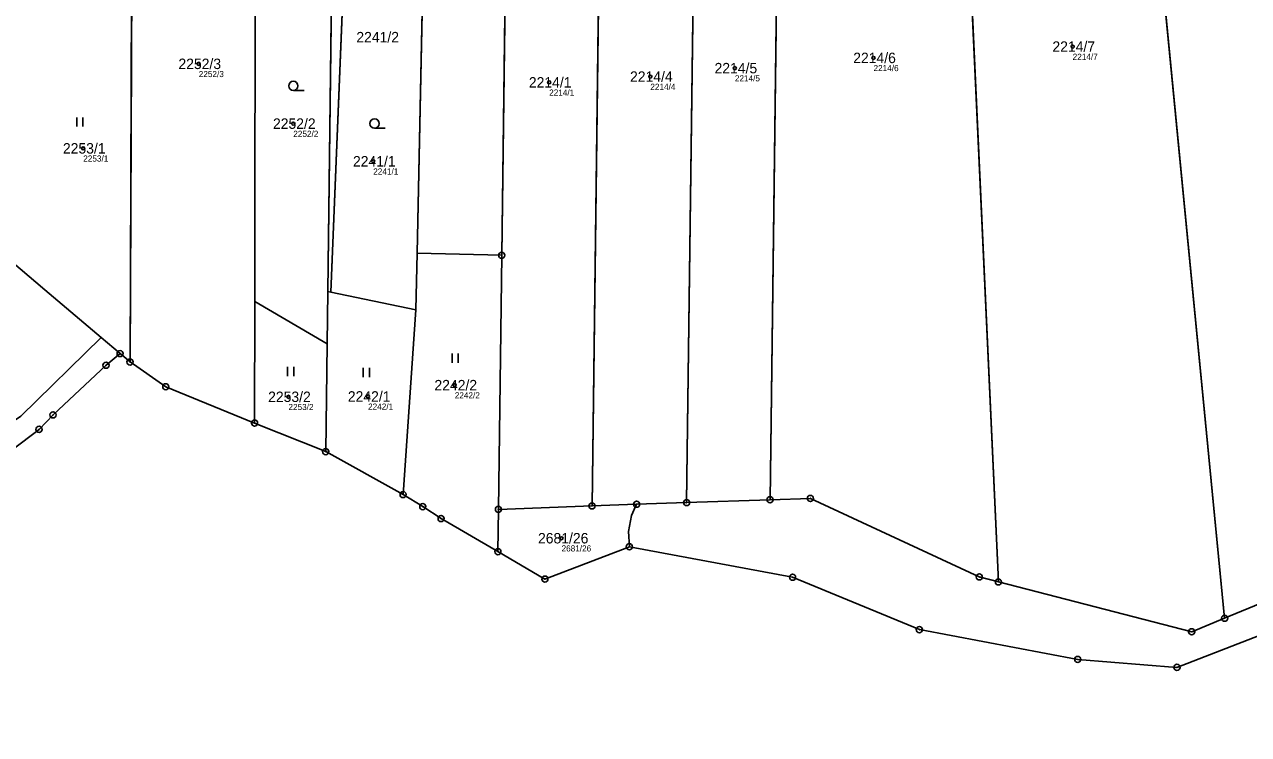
# Model space of a CAD drawing. Extents: x -758777 to -757896, y -1175225 to -1174486.
# Drawn here: x -758235.7 to -758036.1, y -1174949 to -1174833.4 of the extents above; entities that cross this region are included whole.
import ezdxf

# ---------------------------------------------------------------- set-up
doc = ezdxf.new("R2010")
doc.units = 0
for name, color, linetype in [('Definiční body', 7, 'Continuous'), ('Hranice parcel', 7, 'Continuous'), ('Parcelní čísla', 7, 'Continuous'), ('Polygon parcely', 7, 'Continuous'), ('Značky bodu BP', 7, 'Continuous'), ('Značky kultur', 7, 'Continuous')]:
    doc.layers.add(name, color=color, linetype=linetype)

msp = doc.modelspace()

# ---------------------------------------------------------------- linework, layer by layer
at = {"layer": 'Definiční body'}
for centre in [(-758064.8, -1174836.96), (-758207.25, -1174839.77), (-758097.26, -1174838.8), (-758133.64, -1174841.85), (-758119.86, -1174840.47), (-758150.13, -1174842.79), (-758191.84, -1174849.51), (-758226.08, -1174853.54), (-758178.81, -1174855.65), (-758165.52, -1174892.12), (-758192.63, -1174894.02), (-758179.65, -1174893.96), (-758148.11, -1174917.06)]:
    msp.add_circle(centre, 0.25, dxfattribs=at)
at = {"layer": 'Hranice parcel'}
for p, q in [((-758056.09, -1174765.35), (-758040.03, -1174930.09)), ((-758076.9, -1174924.17), (-758083.84, -1174772.54)), ((-758156.63, -1174775.13), (-758157.87, -1174870.96)), ((-758143.14, -1174911.79), (-758141.37, -1174774.78)), ((-758127.73, -1174911.25), (-758125.97, -1174774.42)), ((-758114.13, -1174910.8), (-758112.36, -1174774.1)), ((-758186.22, -1174876.87), (-758185.53, -1174823.65)), ((-758183.53, -1174823.59), (-758185.73, -1174876.96)), ((-758170.66, -1174823.2), (-758171.67, -1174870.63)), ((-758218.18, -1174826.63), (-758218.45, -1174888.34)), ((-758171.67, -1174870.63), (-758171.87, -1174879.84)), ((-758171.67, -1174870.63), (-758157.87, -1174870.96)), ((-758157.87, -1174870.96), (-758158.4, -1174912.36)), ((-758186.32, -1174885.38), (-758186.22, -1174876.87)), ((-758186.22, -1174876.87), (-758185.73, -1174876.96)), ((-758185.73, -1174876.96), (-758171.87, -1174879.84)), ((-758198.15, -1174898.31), (-758198.12, -1174878.49)), ((-758198.12, -1174878.49), (-758186.32, -1174885.38)), ((-758171.87, -1174879.84), (-758173.93, -1174909.94)), ((-758223.14, -1174884.37), (-758220.06, -1174886.98)), ((-758186.55, -1174902.95), (-758186.32, -1174885.38)), ((-758220.06, -1174886.98), (-758218.45, -1174888.34)), ((-758198.15, -1174898.31), (-758186.55, -1174902.95)), ((-758173.93, -1174909.94), (-758186.55, -1174902.95)), ((-758143.14, -1174911.79), (-758135.88, -1174911.52)), ((-758135.88, -1174911.52), (-758127.73, -1174911.25)), ((-758127.73, -1174911.25), (-758114.13, -1174910.8)), ((-758158.49, -1174919.25), (-758158.4, -1174912.36)), ((-758158.4, -1174912.36), (-758143.14, -1174911.79))]:
    msp.add_line(p, q, dxfattribs=at)
for points in [[(-758198.02, -1174777.55), (-758198.11, -1174871.18), (-758198.12, -1174878.49)], [(-758238.89, -1174870.98), (-758232.33, -1174876.61), (-758223.14, -1174884.37)], [(-758302.92, -1174935.57), (-758286.99, -1174927.44), (-758267.9, -1174916.47), (-758249.14, -1174905.98), (-758236.24, -1174897.16), (-758223.14, -1174884.37)], [(-758269.21, -1174920.77), (-758246.51, -1174909.26), (-758233.28, -1174899.33), (-758231, -1174896.96), (-758222.36, -1174888.88), (-758220.06, -1174886.98)], [(-758218.45, -1174888.34), (-758212.63, -1174892.38), (-758198.15, -1174898.31)], [(-758173.93, -1174909.94), (-758170.73, -1174911.91), (-758167.75, -1174913.86), (-758158.49, -1174919.25)], [(-758137.06, -1174918.45), (-758137.2, -1174915.99), (-758136.71, -1174913.36), (-758135.88, -1174911.52)], [(-758114.13, -1174910.8), (-758107.54, -1174910.58), (-758080.03, -1174923.36), (-758076.9, -1174924.17)], [(-758137.06, -1174918.45), (-758150.82, -1174923.72), (-758158.49, -1174919.25)], [(-757896.26, -1174949.04), (-757939.8, -1174930.25), (-757949.26, -1174927.98), (-757957.21, -1174927.28), (-758013.54, -1174927.25), (-758023.59, -1174928.73), (-758047.8, -1174938.11), (-758063.96, -1174936.81), (-758089.79, -1174931.96), (-758110.46, -1174923.41), (-758137.06, -1174918.45)], [(-758040.03, -1174930.09), (-758021.7, -1174922.52), (-757966.21, -1174921.06)], [(-758076.9, -1174924.17), (-758045.39, -1174932.31), (-758040.03, -1174930.09)]]:
    msp.add_lwpolyline(points, dxfattribs=at)
at = {"layer": 'Polygon parcely'}
for points in [[(-758000.82, -1174750.62), (-758030.99, -1174761.66), (-758038.84, -1174760.87), (-758056.09, -1174765.35), (-758040.03, -1174930.09), (-758021.7, -1174922.52), (-757966.21, -1174921.06), (-757991.64, -1174752.6)], [(-758040.03, -1174930.09), (-758056.09, -1174765.35), (-758083.84, -1174772.54), (-758076.9, -1174924.17), (-758045.39, -1174932.31)], [(-758107.54, -1174910.58), (-758080.03, -1174923.36), (-758076.9, -1174924.17), (-758083.84, -1174772.54), (-758087.64, -1174773.53), (-758112.36, -1174774.1), (-758114.13, -1174910.8)], [(-758184.92, -1174776.46), (-758183.9, -1174806.95), (-758179.06, -1174806.83), (-758171.11, -1174806.65), (-758171, -1174811.35), (-758170.9, -1174815.15), (-758170.66, -1174823.2), (-758171.67, -1174870.63), (-758157.87, -1174870.96), (-758156.63, -1174775.13), (-758157.99, -1174775.16)], [(-758143.14, -1174911.79), (-758141.37, -1174774.78), (-758156.63, -1174775.13), (-758157.87, -1174870.96), (-758158.4, -1174912.36)], [(-758127.73, -1174911.25), (-758125.97, -1174774.42), (-758141.37, -1174774.78), (-758143.14, -1174911.79), (-758135.88, -1174911.52)], [(-758114.13, -1174910.8), (-758112.36, -1174774.1), (-758125.97, -1174774.42), (-758127.73, -1174911.25)], [(-758210.07, -1174778.13), (-758217.96, -1174778.94), (-758218.18, -1174826.63), (-758218.45, -1174888.34), (-758212.63, -1174892.38), (-758198.15, -1174898.31), (-758198.12, -1174878.49), (-758198.11, -1174871.18), (-758198.02, -1174777.55)], [(-758198.02, -1174777.55), (-758198.11, -1174871.18), (-758198.12, -1174878.49), (-758186.32, -1174885.38), (-758186.22, -1174876.87), (-758185.53, -1174823.65), (-758185.31, -1174806.74), (-758184.92, -1174776.46)], [(-758185.53, -1174823.65), (-758186.22, -1174876.87), (-758185.73, -1174876.96), (-758183.53, -1174823.59)], [(-758171.87, -1174879.84), (-758171.67, -1174870.63), (-758170.66, -1174823.2), (-758178.71, -1174823.44), (-758183.53, -1174823.59), (-758185.73, -1174876.96)], [(-758220.06, -1174886.98), (-758218.45, -1174888.34), (-758218.18, -1174826.63), (-758234.52, -1174826.12), (-758238.86, -1174825.45), (-758238.89, -1174870.98), (-758232.33, -1174876.61), (-758223.14, -1174884.37)], [(-758267.9, -1174916.47), (-758249.14, -1174905.98), (-758236.24, -1174897.16), (-758223.14, -1174884.37), (-758232.33, -1174876.61), (-758238.89, -1174870.98), (-758251.29, -1174860.33), (-758268.21, -1174848.52), (-758283.71, -1174840.27), (-758288.06, -1174837.68), (-758302.03, -1174856.47), (-758310.72, -1174849.73), (-758342.82, -1174885.08), (-758342.36, -1174886.17), (-758316.19, -1174879.95), (-758311.55, -1174899.38), (-758306.92, -1174918.8), (-758302.92, -1174935.57), (-758286.99, -1174927.44)], [(-758171.67, -1174870.63), (-758171.87, -1174879.84), (-758173.93, -1174909.94), (-758170.73, -1174911.91), (-758167.75, -1174913.86), (-758158.49, -1174919.25), (-758158.4, -1174912.36), (-758157.87, -1174870.96)], [(-758173.93, -1174909.94), (-758171.87, -1174879.84), (-758185.73, -1174876.96), (-758186.22, -1174876.87), (-758186.32, -1174885.38), (-758186.55, -1174902.95)], [(-758198.15, -1174898.31), (-758186.55, -1174902.95), (-758186.32, -1174885.38), (-758198.12, -1174878.49)], [(-758233.28, -1174899.33), (-758231, -1174896.96), (-758222.36, -1174888.88), (-758220.06, -1174886.98), (-758223.14, -1174884.37), (-758236.24, -1174897.16), (-758249.14, -1174905.98), (-758267.9, -1174916.47), (-758286.99, -1174927.44), (-758302.92, -1174935.57), (-758302.28, -1174938.23), (-758297.41, -1174937.08), (-758278.62, -1174926.8), (-758276.96, -1174925.54), (-758269.21, -1174920.77), (-758246.51, -1174909.26)], [(-758136.71, -1174913.36), (-758135.88, -1174911.52), (-758143.14, -1174911.79), (-758158.4, -1174912.36), (-758158.49, -1174919.25), (-758150.82, -1174923.72), (-758137.06, -1174918.45), (-758137.2, -1174915.99)]]:
    msp.add_lwpolyline(points, close=True, dxfattribs=at)
for points in [[(-758023.59, -1174928.73), (-758047.8, -1174938.11), (-758063.96, -1174936.81), (-758089.79, -1174931.96), (-758110.46, -1174923.41), (-758137.06, -1174918.45), (-758150.82, -1174923.72), (-758158.49, -1174919.25), (-758167.75, -1174913.86), (-758170.73, -1174911.91), (-758173.93, -1174909.94), (-758186.55, -1174902.95), (-758198.15, -1174898.31), (-758212.63, -1174892.38), (-758218.45, -1174888.34), (-758220.06, -1174886.98), (-758222.36, -1174888.88), (-758231, -1174896.96), (-758233.28, -1174899.33), (-758246.51, -1174909.26)], [(-758021.7, -1174922.52), (-758040.03, -1174930.09), (-758045.39, -1174932.31), (-758076.9, -1174924.17), (-758080.03, -1174923.36), (-758107.54, -1174910.58), (-758114.13, -1174910.8), (-758127.73, -1174911.25), (-758135.88, -1174911.52), (-758136.71, -1174913.36), (-758137.2, -1174915.99), (-758137.06, -1174918.45), (-758110.46, -1174923.41), (-758089.79, -1174931.96), (-758063.96, -1174936.81), (-758047.8, -1174938.11), (-758023.59, -1174928.73)]]:
    msp.add_lwpolyline(points, dxfattribs=at)
at = {"layer": 'Značky bodu BP'}
for centre, radius in [((-758157.87, -1174870.96), 0.5), ((-758157.87, -1174870.96), 0.0303), ((-758220.06, -1174886.98), 0.5), ((-758220.06, -1174886.98), 0.0303), ((-758222.36, -1174888.88), 0.5), ((-758222.36, -1174888.88), 0.0303), ((-758218.45, -1174888.34), 0.5), ((-758218.45, -1174888.34), 0.0303), ((-758212.63, -1174892.38), 0.5), ((-758212.63, -1174892.38), 0.0303), ((-758231, -1174896.96), 0.5), ((-758231, -1174896.96), 0.0303), ((-758233.28, -1174899.33), 0.5), ((-758233.28, -1174899.33), 0.0303), ((-758198.15, -1174898.31), 0.5), ((-758198.15, -1174898.31), 0.0303), ((-758186.55, -1174902.95), 0.5), ((-758186.55, -1174902.95), 0.0303), ((-758173.93, -1174909.94), 0.5), ((-758173.93, -1174909.94), 0.0303), ((-758170.73, -1174911.91), 0.5), ((-758143.14, -1174911.79), 0.5), ((-758135.88, -1174911.52), 0.5), ((-758135.88, -1174911.52), 0.0303), ((-758127.73, -1174911.25), 0.5), ((-758127.73, -1174911.25), 0.0303), ((-758114.13, -1174910.8), 0.5), ((-758114.13, -1174910.8), 0.0303), ((-758107.54, -1174910.58), 0.5), ((-758107.54, -1174910.58), 0.0303), ((-758170.73, -1174911.91), 0.0303), ((-758167.75, -1174913.86), 0.5), ((-758158.4, -1174912.36), 0.5), ((-758158.4, -1174912.36), 0.0303), ((-758143.14, -1174911.79), 0.0303), ((-758167.75, -1174913.86), 0.0303), ((-758158.49, -1174919.25), 0.5), ((-758158.49, -1174919.25), 0.0303), ((-758137.06, -1174918.45), 0.5), ((-758137.06, -1174918.45), 0.0303), ((-758150.82, -1174923.72), 0.5), ((-758110.46, -1174923.41), 0.5), ((-758110.46, -1174923.41), 0.0303), ((-758080.03, -1174923.36), 0.5), ((-758080.03, -1174923.36), 0.0303), ((-758150.82, -1174923.72), 0.0303), ((-758076.9, -1174924.17), 0.5), ((-758076.9, -1174924.17), 0.0303), ((-758089.79, -1174931.96), 0.5), ((-758040.03, -1174930.09), 0.5), ((-758040.03, -1174930.09), 0.0303), ((-758089.79, -1174931.96), 0.0303), ((-758045.39, -1174932.31), 0.5), ((-758045.39, -1174932.31), 0.0303), ((-758063.96, -1174936.81), 0.5), ((-758063.96, -1174936.81), 0.0303), ((-758047.8, -1174938.11), 0.5), ((-758047.8, -1174938.11), 0.0303)]:
    msp.add_circle(centre, radius, dxfattribs=at)
at = {"layer": 'Značky kultur'}
for p, q in [((-758191.83, -1174844.11), (-758190.08, -1174844.11)), ((-758227.13, -1174849.99), (-758227.13, -1174848.49)), ((-758226.13, -1174849.99), (-758226.13, -1174848.49)), ((-758178.59, -1174850.25), (-758176.84, -1174850.25)), ((-758165.95, -1174888.49), (-758165.95, -1174886.99)), ((-758164.95, -1174888.49), (-758164.95, -1174886.99)), ((-758192.77, -1174890.64), (-758192.77, -1174889.14)), ((-758191.77, -1174890.64), (-758191.77, -1174889.14)), ((-758180.43, -1174890.81), (-758180.43, -1174889.31)), ((-758179.43, -1174890.81), (-758179.43, -1174889.31))]:
    msp.add_line(p, q, dxfattribs=at)
for centre in [(-758191.83, -1174843.36), (-758178.59, -1174849.5)]:
    msp.add_circle(centre, 0.75, dxfattribs=at)

# ---------------------------------------------------------------- texts
at = {"layer": 'Definiční body'}
for s, p in [('2214/7', (-758064.8, -1174839.12)), ('2252/3', (-758207.25, -1174841.93)), ('2214/5', (-758119.86, -1174842.63)), ('2214/6', (-758097.26, -1174840.96)), ('2214/4', (-758133.64, -1174844.01)), ('2214/1', (-758150.13, -1174844.95)), ('2252/2', (-758191.84, -1174851.67)), ('2253/1', (-758226.08, -1174855.7)), ('2241/1', (-758178.81, -1174857.81)), ('2242/2', (-758165.52, -1174894.28)), ('2253/2', (-758192.63, -1174896.18)), ('2242/1', (-758179.65, -1174896.12)), ('2681/26', (-758148.11, -1174919.22))]:
    msp.add_text(s, height=1, dxfattribs=at).set_placement(p)
at = {"layer": 'Parcelní čísla'}
for s, p in [('2241/2', (-758181.56, -1174836.27)), ('2214/7', (-758068.1, -1174837.81)), ('2252/3', (-758210.56, -1174840.62)), ('2214/5', (-758123.17, -1174841.32)), ('2214/6', (-758100.57, -1174839.65)), ('2214/4', (-758136.95, -1174842.7)), ('2214/1', (-758153.44, -1174843.64)), ('2252/2', (-758195.15, -1174850.36)), ('2253/1', (-758229.39, -1174854.39)), ('2241/1', (-758182.11, -1174856.5)), ('2242/2', (-758168.83, -1174892.97)), ('2253/2', (-758195.94, -1174894.87)), ('2242/1', (-758182.95, -1174894.81)), ('2681/26', (-758151.95, -1174917.91))]:
    msp.add_text(s, height=1.7, dxfattribs=at).set_placement(p)

doc.saveas('drawing.dxf')
